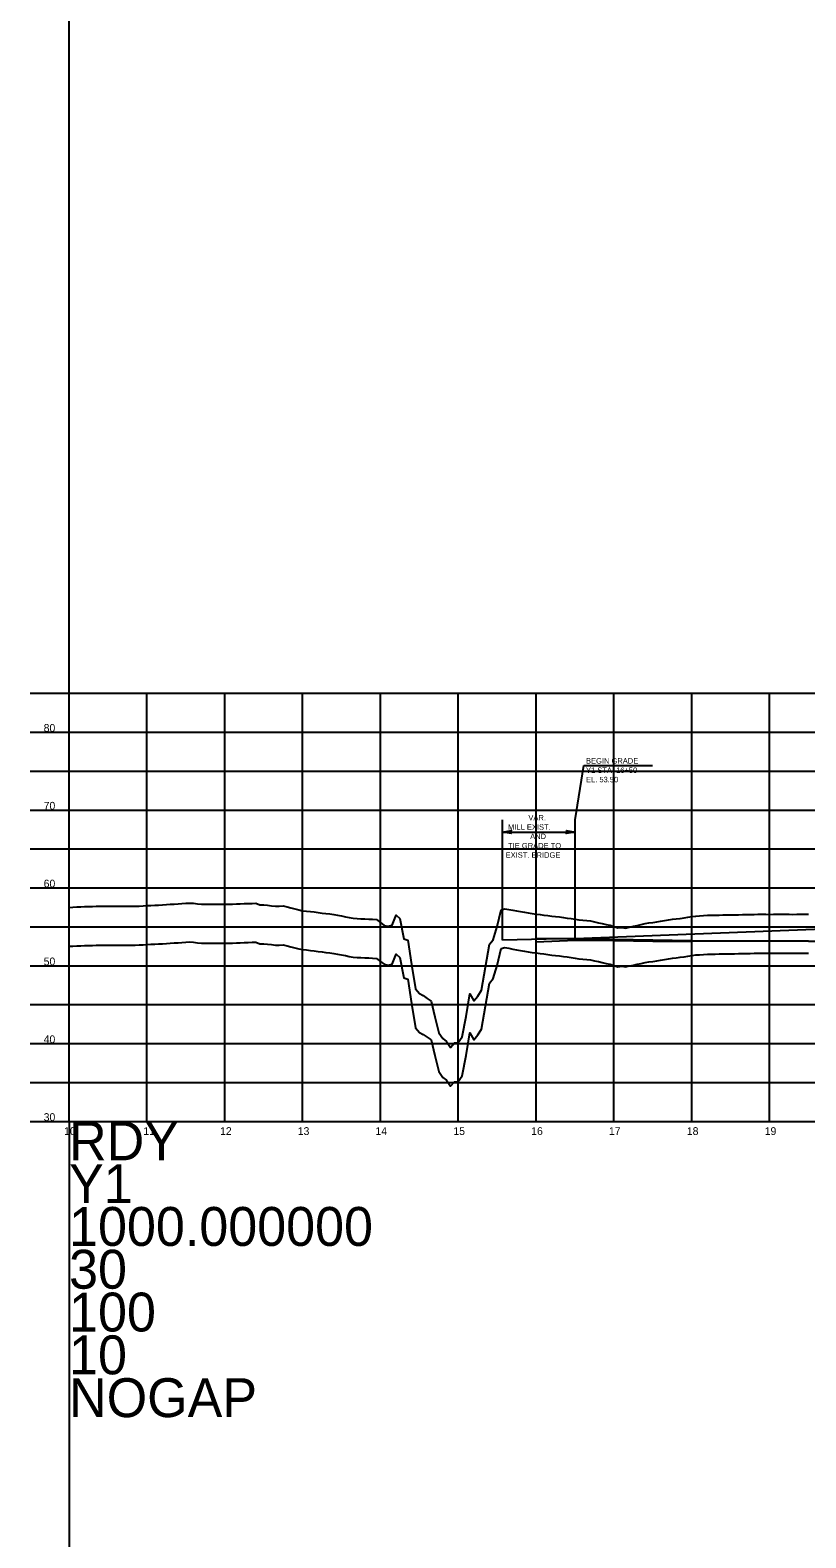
# Model space of a CAD drawing. Extents: x 2345490 to 2445302, y 465165 to 573888.
# Drawn here: x 2381272 to 2382268, y 557249 to 559186 of the extents above; entities that cross this region are included whole.
import ezdxf

# ---------------------------------------------------------------- set-up
doc = ezdxf.new("R2010")
doc.units = 0
for name, color, linetype in [('Old_Level_1', 7, 'Continuous'), ('Old_Level_11', 7, 'Continuous'), ('Old_Level_2', 7, 'Continuous'), ('Old_Level_3', 7, 'Continuous'), ('Old_Level_57', 7, 'Continuous'), ('Old_Level_62', 7, 'Continuous'), ('Old_Level_63', 7, 'Continuous')]:
    doc.layers.add(name, color=color, linetype=linetype)

msp = doc.modelspace()

# ---------------------------------------------------------------- linework, layer by layer
at = {"layer": 'Old_Level_1'}
for points in [[(2381321.5425, 558009.107), (2381326.5425, 558009.354), (2381331.5425, 558009.60075), (2381336.5425, 558009.84775), (2381341.5425, 558010.09475), (2381346.5425, 558010.1735), (2381351.5425, 558010.25575), (2381356.5425, 558010.41725), (2381361.5425, 558010.42925), (2381366.5425, 558010.44125), (2381371.5425, 558010.4535), (2381376.5425, 558010.4655), (2381381.5425, 558010.5355), (2381386.5425, 558010.67525), (2381391.5425, 558010.67975), (2381396.5425, 558010.68425), (2381401.5425, 558010.68875), (2381406.5425, 558010.69325), (2381411.5425, 558010.73825), (2381416.5425, 558010.99525), (2381421.5425, 558011.308), (2381426.5425, 558011.62075), (2381431.5425, 558011.9335), (2381436.5425, 558012.05625), (2381441.5425, 558012.3695), (2381446.5425, 558012.6885), (2381451.5425, 558013.0075), (2381456.5425, 558013.32625), (2381461.5425, 558013.64525), (2381466.5425, 558013.97425), (2381471.5425, 558014.37925), (2381476.5425, 558014.6025), (2381481.5425, 558014.3615), (2381486.5425, 558013.674), (2381491.5425, 558013.0375), (2381496.5425, 558013.0435), (2381501.5425, 558013.107), (2381506.5425, 558013.11175), (2381511.5425, 558013.1165), (2381516.5425, 558013.12125), (2381521.5425, 558013.12575), (2381526.5425, 558013.1305), (2381531.5425, 558013.29325), (2381536.5425, 558013.51425), (2381541.5425, 558013.684), (2381546.5425, 558013.84925), (2381551.5425, 558014.0145), (2381556.5425, 558014.17975), (2381561.5425, 558014.345), (2381566.5425, 558012.34825), (2381571.5425, 558012.16725), (2381576.5425, 558011.94), (2381581.5425, 558011.17425), (2381586.5425, 558010.51125), (2381591.5425, 558010.687), (2381596.5425, 558011.06275), (2381601.5425, 558009.82075), (2381606.5425, 558008.45275), (2381611.5425, 558007.08475), (2381616.5425, 558005.71675), (2381621.5425, 558004.79225), (2381626.5425, 558004.3155), (2381631.5425, 558003.8705), (2381636.5425, 558003.1865), (2381641.5425, 558002.5025), (2381646.5425, 558001.8185), (2381651.5425, 558001.13425), (2381656.5425, 558000.66125), (2381661.5425, 557999.9125), (2381666.5425, 557998.971), (2381671.5425, 557998.0295), (2381676.5425, 557997.08775), (2381681.5425, 557996.14625), (2381686.5425, 557995.2045), (2381691.5425, 557994.73), (2381696.5425, 557994.4985), (2381701.5425, 557994.267), (2381706.5425, 557994.0355), (2381711.5425, 557993.804), (2381716.5425, 557993.32975), (2381721.5425, 557989.6355), (2381726.5425, 557985.94125), (2381731.5425, 557984.98625), (2381736.5425, 557986.2335), (2381741.5425, 557999.0015), (2381746.5425, 557994.703), (2381751.5425, 557968.47525), (2381756.5425, 557966.72025), (2381761.5425, 557935.573), (2381766.5425, 557904.265), (2381771.5425, 557898.2835), (2381776.5425, 557895.816), (2381781.5425, 557892.12), (2381786.5425, 557888.74425), (2381791.5425, 557868.562), (2381796.5425, 557848.07025), (2381801.5425, 557840.46725), (2381806.5425, 557836.9425), (2381811.5425, 557829.2295), (2381816.5425, 557834.94425), (2381821.5425, 557835.4735)], [(2381821.5425, 557835.4735), (2381826.5425, 557842.55175), (2381831.5425, 557868.86125), (2381836.5425, 557897.972), (2381841.5425, 557888.876), (2381846.5425, 557895.1565), (2381851.5425, 557902.77325), (2381856.5425, 557932.17375), (2381861.5425, 557961.7105), (2381866.5425, 557967.49875), (2381871.5425, 557984.313), (2381876.5425, 558006.1115), (2381881.5425, 558007.383), (2381886.5425, 558006.46575), (2381891.5425, 558005.54825), (2381896.5425, 558004.631), (2381901.5425, 558003.71375), (2381906.5425, 558002.83775), (2381911.5425, 558002.06725), (2381916.5425, 558001.172), (2381921.5425, 558000.54175), (2381926.5425, 557999.8575), (2381931.5425, 557999.1735), (2381936.5425, 557998.48925), (2381941.5425, 557997.805), (2381946.5425, 557997.179), (2381951.5425, 557996.79725), (2381956.5425, 557996.081), (2381961.5425, 557995.3495), (2381966.5425, 557994.61775), (2381971.5425, 557993.886), (2381976.5425, 557993.1545), (2381981.5425, 557992.68725), (2381986.5425, 557992.0265), (2381991.5425, 557991.646), (2381996.5425, 557990.494), (2382001.5425, 557989.34175), (2382006.5425, 557988.18975), (2382011.5425, 557987.0375), (2382016.5425, 557985.99625), (2382021.5425, 557984.32225), (2382026.5425, 557982.6485), (2382031.5425, 557983.37), (2382036.5425, 557982.47925), (2382041.5425, 557983.745), (2382046.5425, 557984.8645), (2382051.5425, 557985.98375), (2382056.5425, 557987.103), (2382061.5425, 557988.22225), (2382066.5425, 557989.268), (2382071.5425, 557989.69), (2382076.5425, 557990.5245), (2382081.5425, 557991.359), (2382086.5425, 557992.19325), (2382091.5425, 557993.02775), (2382096.5425, 557993.7575), (2382101.5425, 557994.17975), (2382106.5425, 557994.94725), (2382111.5425, 557995.6835), (2382116.5425, 557996.4195), (2382121.5425, 557997.15575), (2382126.5425, 557997.89175), (2382131.5425, 557998.0865), (2382136.5425, 557998.51875), (2382141.5425, 557999.01325), (2382146.5425, 557999.0895), (2382151.5425, 557999.16075), (2382156.5425, 557999.23225), (2382161.5425, 557999.30375), (2382166.5425, 557999.38925), (2382171.5425, 557999.4855), (2382176.5425, 557999.565), (2382181.5425, 557999.64425), (2382186.5425, 557999.7415), (2382191.5425, 557999.83875), (2382196.5425, 557999.9775), (2382201.5425, 558000.11825), (2382206.5425, 558000.25875), (2382211.5425, 558000.34), (2382216.5425, 558000.1565), (2382221.5425, 558000.06275), (2382226.5425, 558000.18825), (2382231.5425, 558000.314), (2382236.5425, 558000.4395), (2382241.5425, 558000.35), (2382246.5425, 558000.15375), (2382251.5425, 558000.0405), (2382256.5425, 558000.16975), (2382261.5425, 558000.278), (2382266.5425, 558000.263), (2382271.5425, 558000.3275)]]:
    msp.add_lwpolyline(points, dxfattribs=at)
at = {"layer": 'Old_Level_11'}
for points in [[(2381889.7165, 558153.94875), (2381878.4665, 558155.88625), (2381889.779, 558157.88625), (2381888.3415, 558155.88625)], [(2381960.2925, 558157.82375), (2381971.5425, 558155.88625), (2381960.23, 558153.88625), (2381961.6675, 558155.88625)]]:
    msp.add_lwpolyline(points, close=True, dxfattribs=at)
at = {"layer": 'Old_Level_2'}
for q in [(2382671.5425, 558046.335), (2381878.4665, 558016.9915)]:
    msp.add_line((2381971.5425, 558019.113), q, dxfattribs=at)
at = {"layer": 'Old_Level_3'}
for p, q in [((2381971.5425, 558171.59525), (2381982.94325, 558241.3935)), ((2381982.94325, 558241.3935), (2382071.25325, 558241.3935)), ((2381878.4665, 558016.9915), (2381878.4665, 558171.59525)), ((2381971.5425, 558019.113), (2381971.5425, 558171.59525)), ((2381878.4665, 558155.88625), (2381971.5425, 558155.88625))]:
    msp.add_line(p, q, dxfattribs=at)
at = {"layer": 'Old_Level_57'}
for p, q in [((2381271.54275, 558334.11325), (2393041.55275, 558334.11325)), ((2381321.54225, 557784.21325), (2381321.54225, 558334.21325)), ((2381321.54225, 557784.11325), (2381321.54225, 558334.11325)), ((2381421.54225, 557784.21325), (2381421.54225, 558334.21325)), ((2381421.54225, 557784.11325), (2381421.54225, 558334.11325)), ((2381521.54225, 557784.21325), (2381521.54225, 558334.21325)), ((2381521.54225, 557784.11325), (2381521.54225, 558334.11325)), ((2381621.54225, 557784.21325), (2381621.54225, 558334.21325)), ((2381621.54225, 557784.11325), (2381621.54225, 558334.11325)), ((2381721.54225, 557784.21325), (2381721.54225, 558334.21325)), ((2381721.54225, 557784.11325), (2381721.54225, 558334.11325)), ((2381821.54225, 557784.21325), (2381821.54225, 558334.21325)), ((2381821.54225, 557784.11325), (2381821.54225, 558334.11325)), ((2381921.54225, 557784.21325), (2381921.54225, 558334.21325)), ((2381921.54225, 557784.11325), (2381921.54225, 558334.11325)), ((2382021.54225, 557784.21325), (2382021.54225, 558334.21325)), ((2382021.54225, 557784.11325), (2382021.54225, 558334.11325)), ((2382121.54225, 557784.21325), (2382121.54225, 558334.21325)), ((2382121.54225, 557784.11325), (2382121.54225, 558334.11325)), ((2382221.54225, 557784.21325), (2382221.54225, 558334.21325)), ((2382221.54225, 557784.11325), (2382221.54225, 558334.11325)), ((2381271.54275, 558284.11325), (2393041.55275, 558284.11325)), ((2381271.54275, 558234.11325), (2393041.55275, 558234.11325)), ((2381271.54275, 558184.11325), (2393041.55275, 558184.11325)), ((2381271.54275, 558134.11325), (2393041.55275, 558134.11325)), ((2381271.54275, 558084.11325), (2393041.55275, 558084.11325)), ((2381271.5425, 558034.11325), (2393041.55275, 558034.11325)), ((2381271.54275, 557984.11325), (2393041.55275, 557984.11325)), ((2381271.5425, 557934.11325), (2393041.55275, 557934.11325)), ((2381271.54275, 557884.11325), (2393041.55275, 557884.11325)), ((2381271.5425, 557834.11325), (2393041.55275, 557834.11325)), ((2381271.54275, 557784.11325), (2393041.55275, 557784.11325))]:
    msp.add_line(p, q, dxfattribs=at)
at = {"layer": 'Old_Level_62'}
for points in [[(2381321.5425, 558059.113), (2381326.5425, 558059.36), (2381331.5425, 558059.60675), (2381336.5425, 558059.85375), (2381341.5425, 558060.10075), (2381346.5425, 558060.1795), (2381351.5425, 558060.26175), (2381356.5425, 558060.42325), (2381361.5425, 558060.43525), (2381366.5425, 558060.44725), (2381371.5425, 558060.4595), (2381376.5425, 558060.4715), (2381381.5425, 558060.5415), (2381386.5425, 558060.68125), (2381391.5425, 558060.68575), (2381396.5425, 558060.69025), (2381401.5425, 558060.69475), (2381406.5425, 558060.69925), (2381411.5425, 558060.74425), (2381416.5425, 558061.00125), (2381421.5425, 558061.314), (2381426.5425, 558061.62675), (2381431.5425, 558061.9395), (2381436.5425, 558062.06225), (2381441.5425, 558062.3755), (2381446.5425, 558062.6945), (2381451.5425, 558063.0135), (2381456.5425, 558063.33225), (2381461.5425, 558063.65125), (2381466.5425, 558063.98025), (2381471.5425, 558064.38525), (2381476.5425, 558064.6085), (2381481.5425, 558064.3675), (2381486.5425, 558063.68), (2381491.5425, 558063.0435), (2381496.5425, 558063.0495), (2381501.5425, 558063.113), (2381506.5425, 558063.11775), (2381511.5425, 558063.1225), (2381516.5425, 558063.12725), (2381521.5425, 558063.13175), (2381526.5425, 558063.1365), (2381531.5425, 558063.29925), (2381536.5425, 558063.52025), (2381541.5425, 558063.69), (2381546.5425, 558063.85525), (2381551.5425, 558064.0205), (2381556.5425, 558064.18575), (2381561.5425, 558064.351), (2381566.5425, 558062.35425), (2381571.5425, 558062.17325), (2381576.5425, 558061.946), (2381581.5425, 558061.18025), (2381586.5425, 558060.51725), (2381591.5425, 558060.693), (2381596.5425, 558061.06875), (2381601.5425, 558059.82675), (2381606.5425, 558058.45875), (2381611.5425, 558057.09075), (2381616.5425, 558055.72275), (2381621.5425, 558054.79825), (2381626.5425, 558054.3215), (2381631.5425, 558053.8765), (2381636.5425, 558053.1925), (2381641.5425, 558052.5085), (2381646.5425, 558051.8245), (2381651.5425, 558051.14025), (2381656.5425, 558050.66725), (2381661.5425, 558049.9185), (2381666.5425, 558048.977), (2381671.5425, 558048.0355), (2381676.5425, 558047.09375), (2381681.5425, 558046.15225), (2381686.5425, 558045.2105), (2381691.5425, 558044.736), (2381696.5425, 558044.5045), (2381701.5425, 558044.273), (2381706.5425, 558044.0415), (2381711.5425, 558043.81), (2381716.5425, 558043.33575), (2381721.5425, 558039.6415), (2381726.5425, 558035.94725), (2381731.5425, 558034.99225), (2381736.5425, 558036.2395), (2381741.5425, 558049.0075), (2381746.5425, 558044.709), (2381751.5425, 558018.48125), (2381756.5425, 558016.72625), (2381761.5425, 557985.579), (2381766.5425, 557954.271), (2381771.5425, 557948.2895), (2381776.5425, 557945.822), (2381781.5425, 557942.126), (2381786.5425, 557938.75025), (2381791.5425, 557918.568), (2381796.5425, 557898.07625), (2381801.5425, 557890.47325), (2381806.5425, 557886.9485), (2381811.5425, 557879.2355), (2381816.5425, 557884.95025), (2381821.5425, 557885.4795)], [(2381821.5425, 557885.4795), (2381826.5425, 557892.55775), (2381831.5425, 557918.86725), (2381836.5425, 557947.978), (2381841.5425, 557938.882), (2381846.5425, 557945.1625), (2381851.5425, 557952.77925), (2381856.5425, 557982.17975), (2381861.5425, 558011.7165), (2381866.5425, 558017.50475), (2381871.5425, 558034.319), (2381876.5425, 558056.1175), (2381881.5425, 558057.389), (2381886.5425, 558056.47175), (2381891.5425, 558055.55425), (2381896.5425, 558054.637), (2381901.5425, 558053.71975), (2381906.5425, 558052.84375), (2381911.5425, 558052.07325), (2381916.5425, 558051.178), (2381921.5425, 558050.54775), (2381926.5425, 558049.8635), (2381931.5425, 558049.1795), (2381936.5425, 558048.49525), (2381941.5425, 558047.811), (2381946.5425, 558047.185), (2381951.5425, 558046.80325), (2381956.5425, 558046.087), (2381961.5425, 558045.3555), (2381966.5425, 558044.62375), (2381971.5425, 558043.892), (2381976.5425, 558043.1605), (2381981.5425, 558042.69325), (2381986.5425, 558042.0325), (2381991.5425, 558041.652), (2381996.5425, 558040.5), (2382001.5425, 558039.34775), (2382006.5425, 558038.19575), (2382011.5425, 558037.0435), (2382016.5425, 558036.00225), (2382021.5425, 558034.32825), (2382026.5425, 558032.6545), (2382031.5425, 558033.376), (2382036.5425, 558032.48525), (2382041.5425, 558033.751), (2382046.5425, 558034.8705), (2382051.5425, 558035.98975), (2382056.5425, 558037.109), (2382061.5425, 558038.22825), (2382066.5425, 558039.274), (2382071.5425, 558039.696), (2382076.5425, 558040.5305), (2382081.5425, 558041.365), (2382086.5425, 558042.19925), (2382091.5425, 558043.03375), (2382096.5425, 558043.7635), (2382101.5425, 558044.18575), (2382106.5425, 558044.95325), (2382111.5425, 558045.6895), (2382116.5425, 558046.4255), (2382121.5425, 558047.16175), (2382126.5425, 558047.89775), (2382131.5425, 558048.0925), (2382136.5425, 558048.52475), (2382141.5425, 558049.01925), (2382146.5425, 558049.0955), (2382151.5425, 558049.16675), (2382156.5425, 558049.23825), (2382161.5425, 558049.30975), (2382166.5425, 558049.39525), (2382171.5425, 558049.4915), (2382176.5425, 558049.571), (2382181.5425, 558049.65025), (2382186.5425, 558049.7475), (2382191.5425, 558049.84475), (2382196.5425, 558049.9835), (2382201.5425, 558050.12425), (2382206.5425, 558050.26475), (2382211.5425, 558050.346), (2382216.5425, 558050.1625), (2382221.5425, 558050.06875), (2382226.5425, 558050.19425), (2382231.5425, 558050.32), (2382236.5425, 558050.4455), (2382241.5425, 558050.356), (2382246.5425, 558050.15975), (2382251.5425, 558050.0465), (2382256.5425, 558050.17575), (2382261.5425, 558050.284), (2382266.5425, 558050.269), (2382271.5425, 558050.3335)], [(2381921.5425, 558014.613), (2381971.5425, 558017.013), (2382021.5425, 558016.713), (2382071.5425, 558015.713), (2382121.5425, 558015.613), (2382171.5425, 558016.013), (2382221.5425, 558016.113), (2382271.5425, 558015.713), (2382321.5425, 558015.213), (2382371.5425, 558030.313), (2382421.5425, 558029.713), (2382471.5425, 558028.413), (2382521.5425, 558027.213), (2382571.5425, 558026.613), (2382621.5425, 558023.713), (2382671.5425, 558023.013), (2382721.5425, 558021.313)], [(2381921.5425, 558018.913), (2381971.5425, 558019.113), (2382021.5425, 558018.313), (2382071.5425, 558017.413), (2382121.5425, 558016.713), (2382171.5425, 558016.113), (2382221.5425, 558016.013), (2382271.5425, 558016.013), (2382321.5425, 558015.213), (2382371.5425, 558015.013), (2382421.5425, 558013.913), (2382471.5425, 558012.513), (2382521.5425, 558010.713), (2382571.5425, 558005.613), (2382621.5425, 558024.813), (2382671.5425, 558021.113), (2382721.5425, 558017.413), (2382771.5425, 558011.613), (2382821.5425, 558018.413), (2382871.5425, 558022.913), (2382921.5425, 558014.613), (2382971.5425, 558004.513)]]:
    msp.add_lwpolyline(points, dxfattribs=at)
at = {"layer": 'Old_Level_63'}
for q in [(2381321.5425, 560284.113), (2393019.104, 557784.113), (2381321.5425, 555284.113)]:
    msp.add_line((2381321.5425, 557784.113), q, dxfattribs=at)

# ---------------------------------------------------------------- texts
at = {"layer": 'Old_Level_1'}
for s, p in [('80', (2381288.929, 558284.613)), ('70', (2381288.929, 558184.613)), ('60', (2381288.929, 558084.613)), ('50', (2381288.929, 557984.613)), ('40', (2381288.929, 557884.613)), ('30', (2381288.929, 557784.613)), ('10', (2381315.126, 557766.613)), ('11', (2381416.9655, 557766.613)), ('12', (2381515.51375, 557766.613)), ('13', (2381615.3485, 557766.613)), ('14', (2381715.191, 557766.613)), ('15', (2381815.2835, 557766.613)), ('16', (2381915.2245, 557766.613)), ('17', (2382015.082, 557766.613)), ('18', (2382115.20775, 557766.613)), ('19', (2382215.25, 557766.613))]:
    msp.add_text(s, height=10.000001, dxfattribs=at).set_placement(p)
at = {"layer": 'Old_Level_3'}
for s, height, p in [('Y1 STA. 16+50', 7.0000005, (2381985.63675, 558231.789)), ('BEGIN GRADE', 7.0000005, (2381985.63675, 558243.78925)), ('EL. 53.50', 7.000001, (2381985.63675, 558219.789)), ('VAR.', 7.000001, (2381911.578, 558170.8265)), ('MILL EXIST. ', 7.0000005, (2381885.481, 558158.8265)), ('TIE GRADE TO', 7.0000005, (2381885.5145, 558134.82625)), ('AND', 7.000001, (2381913.865, 558146.8265)), ('EXIST. BRIDGE', 7.0000005, (2381882.368, 558122.82625))]:
    msp.add_text(s, height=height, dxfattribs=at).set_placement(p)
at = {"layer": 'Old_Level_63'}
for s, height, p in [('RDY', 50, (2381321.5425, 557734.113)), ('Y1', 50, (2381321.5425, 557679.113)), ('1000.000000', 49.9999995, (2381321.5425, 557624.113)), ('30', 50, (2381321.5425, 557569.113)), ('100', 50, (2381321.5425, 557514.113)), ('10', 50, (2381321.5425, 557459.113)), ('NOGAP', 50, (2381321.5425, 557404.113))]:
    msp.add_text(s, height=height, dxfattribs=at).set_placement(p)

doc.saveas('drawing.dxf')
